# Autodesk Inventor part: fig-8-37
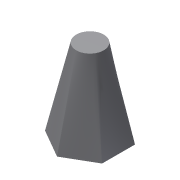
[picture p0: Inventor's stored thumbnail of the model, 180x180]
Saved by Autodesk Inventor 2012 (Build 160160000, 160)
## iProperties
Created: 2007-05
Part Number: fig-8-37
Document SubType Name: Modeling
Designer: Administrator
Density: 1 g/cm^3
Material: Default
Author: Administrator
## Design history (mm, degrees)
sketch "Sketch1"
  geometry: L1 (0, 30)-(25.981, 15); L2 (25.981, 15)-(25.981, -15); L3 (25.981, -15)-(0, -30); L4 (0, -30)-(-25.981, -15); L5 (-25.981, -15)-(-25.981, 15); L6 (-25.981, 15)-(0, 30); 2 further points
  constraints: 12 end point, 1 coincident, 1 vertical, 14 other
workplane "Work Plane1"
sketch "Sketch2"
  geometry: C1 r 12.5 at (0, 0)
  constraints: 1 centre point, 1 other
sketch "Sketch3"
  geometry: L1 (0, 0)-(0, 75)
  constraints: 2 end point, 1 vertical, 1 other
loft "Loft1" dims "d5" = 0, "d6" = 90 deg, "d7" = 0, "d8" = 90 deg
body "Solid1"
other parameters: "d1" = 75
